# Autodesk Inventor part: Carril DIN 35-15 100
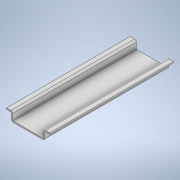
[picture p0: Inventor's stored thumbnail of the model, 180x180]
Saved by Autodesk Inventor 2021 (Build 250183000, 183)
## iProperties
Created: 2021-06
Part Number: Carril DIN 35-15 100
Material: Genérico
Document SubType Name: Modeling
Designer: ATOUZA
Density: 1 g/cm^3
Appearance: Valor por defecto
Author: ATOUZA
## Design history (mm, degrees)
sketch "Boceto1"
  geometry: L1 (0, 0)-(0, 4.5); L2 (-1, 4.5)-(-1, 0); L3 (-1.5, 6)-(-5, 6); L4 (-5, 6)-(-5, 5); L5 (-5, 5)-(-1.5, 5); L6 (15.25, -0.5)-(0.5, -0.5); L7 (0.5, -1.5)-(15.25, -1.5); L8 (15.25, -1.5)-(24.5, -1.5); L9 (24.5, -0.5)-(15.25, -0.5); L10 (25, 4.5)-(25, 0); L11 (26, 0)-(26, 4.5); L12 (26.5, 5)-(30, 5); L13 (30, 5)-(30, 6); L14 (30, 6)-(26.5, 6); A1 r 0.5 centre (-1.5, 4.5) between (-1, 4.5) and (-1.5, 5); A2 r 1.5 centre (-1.5, 4.5) between (0, 4.5) and (-1.5, 6); A3 r 1.5 centre (0.5, 0) between (-1, 0) and (0.5, -1.5); A4 r 0.5 centre (0.5, 0) between (0, 0) and (0.5, -0.5); A5 r 0.5 centre (24.5, 0) between (24.5, -0.5) and (25, 0); A6 r 1.5 centre (24.5, 0) between (24.5, -1.5) and (26, 0); A7 r 0.5 centre (26.5, 4.5) between (26.5, 5) and (26, 4.5); A8 r 1.5 centre (26.5, 4.5) between (26.5, 6) and (25, 4.5); 2 further points
  constraints: 28 end point, 16 point on circle, 8 centre point, 1 collinear, 1 horizontal
extrude "Extrusión1" new body sketch "Boceto1" distance "d0" = 100; taper "d1" = 0 deg
node "Sólido1"
